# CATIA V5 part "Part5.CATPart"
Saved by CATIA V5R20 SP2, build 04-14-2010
Part number: Part5
Bounding box of the stored display mesh (mm): x -35 to 100, y 87.196 to 529.376, z 98.118 to 279.438
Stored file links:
  E:\Ehsan\Amoozesh\CATIA\CATIA Course\Basic\Exercises\Assembly\6\Part5.CATPart
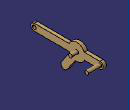
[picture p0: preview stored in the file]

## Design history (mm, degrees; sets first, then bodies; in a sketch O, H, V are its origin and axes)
Body1 (main body)
  Sketch1 on yz-plane, origin (0, 0, 0), H (0, 1, 0), V (0, 0, 1)
    construction line L1 (108.1364, 228.6979) -> (508.4364, 228.6979)
    line L2 (108.1364, 249.6479) -> (321.9233, 249.6479)
    line L3 (508.4364, 207.7479) -> (414.3494, 207.7479)
    arc A1 centre (508.4364, 228.6979) radius 20.95 from (508.4364, 249.6479) to (508.4364, 207.7479) cw
    arc A2 centre (108.1364, 228.6979) radius 20.95 from (108.1364, 207.7479) to (108.1364, 249.6479) cw
    circle A3 centre (508.4364, 228.6979) radius 11.04
    circle A4 centre (108.1364, 228.6979) radius 11.04
    arc A5 centre (368.1364, 228.6979) radius 50.74 from (414.3494, 249.6479) to (321.9233, 249.6479) ccw
    arc A6 centre (368.1364, 228.6979) radius 50.74 from (321.9233, 207.7479) to (324.5046, 202.7978) ccw
    line L4 (414.3494, 249.6479) -> (508.4364, 249.6479)
    line L5 (321.9233, 207.7479) -> (108.1364, 207.7479)
    construction line L6 (368.1364, 228.6979) -> (291.5965, 119.0621)
    line L7 (274.4185, 131.0545) -> (324.5046, 202.7978)
    arc A7 centre (291.5965, 119.0621) radius 20.95 from (308.7745, 107.0696) to (274.4185, 131.0545) cw
    arc A8 centre (368.1364, 228.6979) radius 50.74 from (358.8606, 178.8129) to (414.3494, 207.7479) ccw
    line L8 (358.8606, 178.8129) -> (308.7745, 107.0696)
    circle A9 centre (368.1364, 228.6979) radius 11.04
    circle A10 centre (291.5965, 119.0621) radius 11.04
  MultiPad1: profile Sketch1, domains (length 20; length 20 / length 35; length 60; length 0; length 100)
